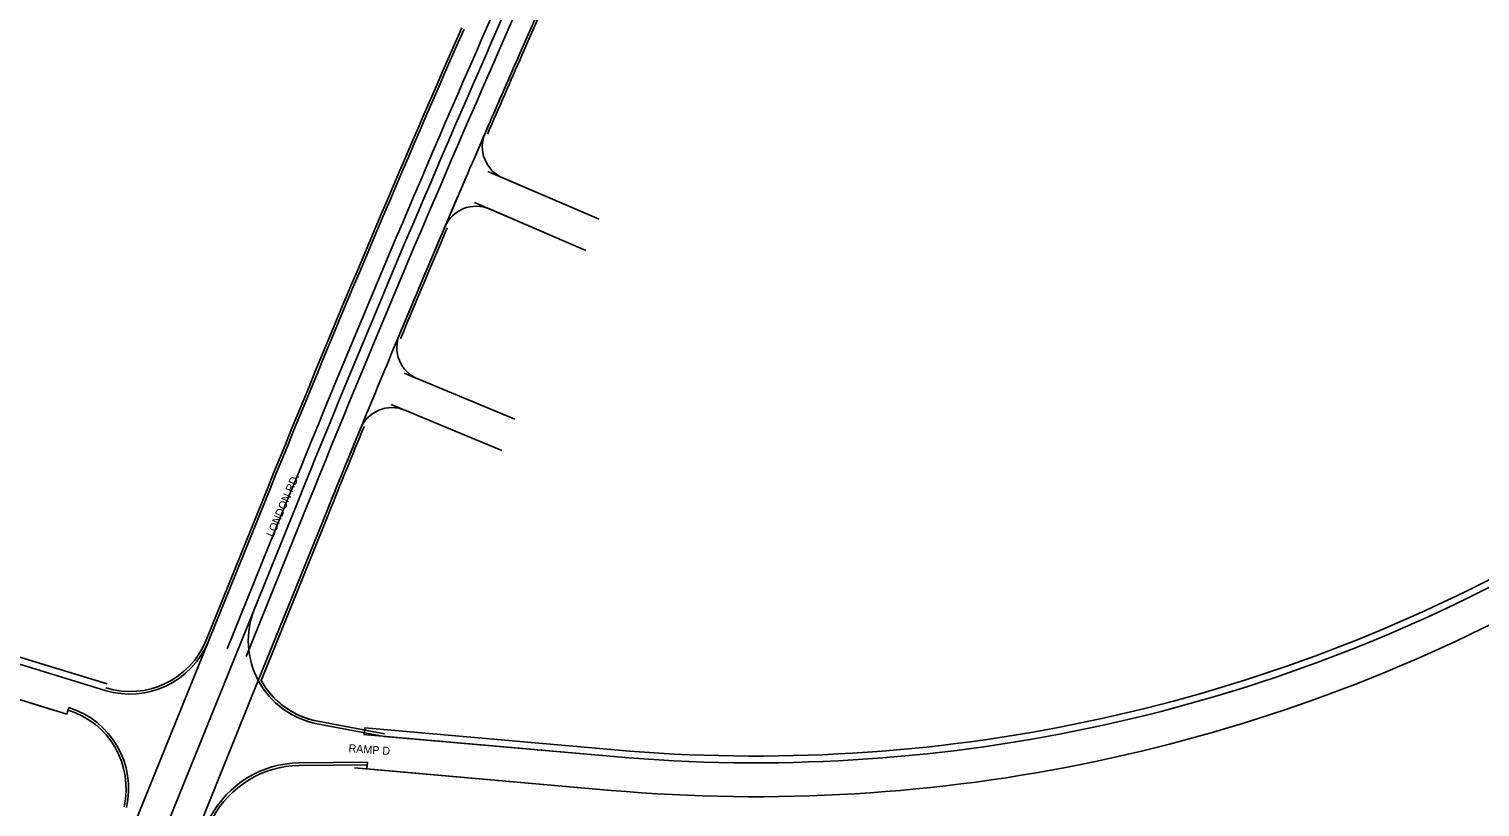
# Model space of a CAD drawing. Extents: x 2315515 to 2326910, y 758186 to 762794.
# Drawn here: x 2320623 to 2321480, y 759540 to 759999 of the extents above; entities that cross this region are included whole.
import ezdxf

# ---------------------------------------------------------------- set-up
doc = ezdxf.new("R2010")
doc.units = 0
for name, color, linetype in [('Default', 7, 'Continuous'), ('E_Terrain_Exterior', 7, 'Continuous'), ('Pavement Marking Yellow', 7, 'Continuous'), ('Road_Curb_Face', 7, 'Continuous'), ('TL_End Condition Ditch In', 7, 'Continuous'), ('TL_Pavement Centerline', 7, 'Continuous')]:
    doc.layers.add(name, color=color, linetype=linetype)

msp = doc.modelspace()

# ---------------------------------------------------------------- linework, layer by layer
at = {"layer": 'Default'}
for p, q in [((2320896.62, 759992.18), (2321353.37, 761032.31)), ((2320896.62, 759992.18), (2321353.37, 761032.31)), ((2320896.62, 759992.18), (2321353.37, 761032.31)), ((2320629.39, 759343.06), (2320782.39, 759721.29)), ((2320629.39, 759343.06), (2320782.39, 759721.29)), ((2320629.39, 759343.06), (2320782.39, 759721.29))]:
    msp.add_line(p, q, dxfattribs=at)
msp.add_arc((2330052.71, 755971.47), 10000, 156.292302, 157.976797, dxfattribs=at)
msp.add_arc((2330052.71, 755971.47), 10000, 156.292302, 157.976797, dxfattribs=at)
msp.add_arc((2330052.71, 755971.47), 10000, 156.292302, 157.976797, dxfattribs=at)
at = {"layer": 'E_Terrain_Exterior'}
for p, q in [((2320913.1, 759984.94), (2321196.22, 760629.68)), ((2320913.1, 759984.94), (2321196.22, 760629.68)), ((2320894.23, 759915.34), (2320959.97, 759887.11)), ((2320903.04, 759911.56), (2320959.97, 759887.11)), ((2320886.34, 759896.96), (2320952.08, 759868.73)), ((2320895.15, 759893.18), (2320952.08, 759868.73)), ((2320844.8, 759796.17), (2320910.07, 759769.14)), ((2320852.83, 759792.85), (2320910.07, 759769.14)), ((2320837.14, 759777.7), (2320902.42, 759750.66)), ((2320845.18, 759774.37), (2320902.42, 759750.66)), ((2320729.28, 759638.01), (2320765.7, 759728.04)), ((2320729.28, 759638.01), (2320765.7, 759728.04)), ((2320758.72, 759614.78), (2320799.07, 759714.54)), ((2320758.72, 759614.78), (2320799.07, 759714.54)), ((2320517.56, 759655.1), (2320668.29, 759608.95)), ((2320832.97, 759581.78), (2320793.48, 759589.27)), ((2320832.97, 759581.78), (2320793.48, 759589.27)), ((2320820.81, 759582.85), (2320968.66, 759569.85)), ((2320832.97, 759581.78), (2320968.66, 759569.85)), ((2320782.76, 759566.12), (2320822.96, 759566.6))]:
    msp.add_line(p, q, dxfattribs=at)
for centre, radius, start, end in [((2330052.71, 755971.47), 10018, 156.292302, 157.976797), ((2330052.71, 755971.47), 10018, 156.292302, 157.976797), ((2330052.71, 755971.47), 9982, 156.292302, 156.670307), ((2330052.71, 755971.47), 9982, 156.292302, 156.587008), ((2320910.93, 759929.93), 20, 156.58701, 246.75955), ((2330052.71, 755971.47), 9982, 156.822087, 157.380681), ((2320887.26, 759874.8), 20, 66.75955, 156.93209), ((2330052.71, 755971.47), 9982, 156.932095, 157.328334), ((2320860.48, 759811.32), 20, 157.32833, 247.50088), ((2330052.71, 755971.47), 9982, 157.607154, 157.976797), ((2320837.52, 759755.89), 20, 67.50088, 157.67342), ((2330052.71, 755971.47), 9982, 157.673421, 157.976797), ((2321052.37, 760522.18), 956, 264.9768, 298.74154), ((2321052.37, 760522.18), 956, 264.9768, 298.74154), ((2320802.79, 759638.39), 50, 157.9768, 259.2662), ((2320682.93, 759656.76), 50, 252.9768, 337.9768), ((2320802.79, 759638.39), 50, 208.18498, 259.2662), ((2320632.19, 759550.98), 50, 347.06707, 72.9768), ((2320783.48, 759506.12), 60, 90.68739, 152.2662)]:
    msp.add_arc(centre, radius, start, end, dxfattribs=at)
at = {"layer": 'Pavement Marking Yellow'}
for p, q in [((2320891.13, 759994.59), (2321173.97, 760638.69)), ((2320902.12, 759989.77), (2321184.96, 760633.86)), ((2320740.41, 759633.51), (2320776.83, 759723.54)), ((2320751.5, 759628.94), (2320787.95, 759719.04))]:
    msp.add_line(p, q, dxfattribs=at)
for radius in [10006, 9994]:
    msp.add_arc((2330052.71, 755971.47), radius, 156.292302, 157.976797, dxfattribs=at)
at = {"layer": 'Road_Curb_Face'}
for p, q in [((2320914.48, 759984.34), (2321197.6, 760629.07)), ((2320727.89, 759638.57), (2320764.31, 759728.61)), ((2320727.89, 759638.57), (2320764.31, 759728.61)), ((2320760.11, 759614.21), (2320800.46, 759713.98)), ((2320760.37, 759614.87), (2320800.46, 759713.98)), ((2320833.25, 759583.25), (2320793.76, 759590.74)), ((2320833.25, 759583.25), (2320793.76, 759590.74)), ((2320782.78, 759564.62), (2320822.98, 759565.1))]:
    msp.add_line(p, q, dxfattribs=at)
for centre, radius, start, end in [((2330052.71, 755971.47), 10019.5, 156.292302, 157.976797), ((2330052.71, 755971.47), 10019.5, 156.292302, 157.976797), ((2330052.71, 755971.47), 9980.5, 156.292302, 156.587008), ((2330052.71, 755971.47), 9980.5, 156.932095, 157.339837), ((2330052.71, 755971.47), 9980.5, 157.661918, 157.976797), ((2330052.71, 755971.47), 9980.5, 157.661918, 157.976797), ((2320682.93, 759656.76), 48.5, 252.9768, 337.9768), ((2320802.79, 759638.39), 48.5, 209.01029, 259.2662), ((2320802.79, 759638.39), 48.5, 212.68872, 259.2662), ((2320632.19, 759550.98), 48.5, 347.06707, 72.9768), ((2320632.19, 759550.98), 48.5, 347.06707, 72.9768), ((2320783.48, 759506.12), 58.5, 90.68739, 152.2662)]:
    msp.add_arc(centre, radius, start, end, dxfattribs=at)
at = {"layer": 'TL_End Condition Ditch In'}
for p, q in [((2320669.59, 759490.43), (2320729.28, 759638.01)), ((2320702.96, 759476.93), (2320758.72, 759614.78))]:
    msp.add_line(p, q, dxfattribs=at)
for start, end in [(156.587008, 156.932095), (157.339837, 157.661918)]:
    msp.add_arc((2330052.71, 755971.47), 9982, start, end, dxfattribs=at)
at = {"layer": 'TL_Pavement Centerline'}
for p, q in [((2320518.73, 759658.92), (2320669.46, 759612.77)), ((2320511.71, 759635.97), (2320638.4, 759597.18)), ((2320511.71, 759635.97), (2320645.66, 759594.96)), ((2320646.83, 759598.79), (2320645.66, 759594.96)), ((2320821.21, 759582.81), (2320821.56, 759586.8)), ((2320821.56, 759586.8), (2320969.01, 759573.84)), ((2320823.16, 759566.58), (2320822.81, 759562.6)), ((2320815.41, 759563.25), (2320966.91, 759549.93)), ((2320822.81, 759562.6), (2320966.91, 759549.93))]:
    msp.add_line(p, q, dxfattribs=at)
for radius in [952, 976, 976]:
    msp.add_arc((2321052.37, 760522.18), radius, 264.9768, 298.74154, dxfattribs=at)

# ---------------------------------------------------------------- texts
at = {"layer": 'Default'}
for s, rotation, p in [('LONDON RD.', 67.08867, (2320767.67, 759699.06)), ('RAMP D', 355.87761, (2320811.83, 759572.53))]:
    msp.add_text(s, height=4.724, rotation=rotation, dxfattribs=at).set_placement(p)

doc.saveas('drawing.dxf')
